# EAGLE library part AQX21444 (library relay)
PhotoMOS Relay NAiS Source: http://www.mew-europe.com/.. pti_en.pdf
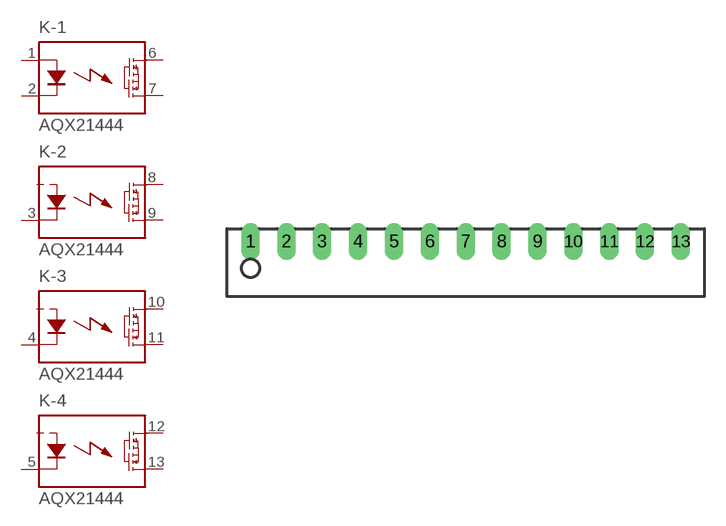
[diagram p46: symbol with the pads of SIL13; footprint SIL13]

Designator prefix K; gates -1=PHOTOMOS_2D -2=PHOTOMOS-DC3 -3=PHOTOMOS-DC3 -4=PHOTOMOS-DC3

## AQX21444 (OC_FARNELL: unknown; OC_NEWARK: unknown)  [SIL13]
1  -1:A  pas
2  -1:K  pas
3  -2:K  pas
4  -3:K  pas
5  -4:K  pas
6  -1:DS1  pas
7  -1:DS2  pas
8  -2:DS1  pas
9  -2:DS2  pas
10  -3:DS1  pas
11  -3:DS2  pas
12  -4:DS1  pas
13  -4:DS2  pas

## Footprint SIL13 (pad centres in mm)
SIL 13 - AQX21.44 Series (Multi-channel) Source: http://www.mew-europe.com/.. pti_en.pdf
drill 0.8 long: 1 -15.24,1.27; 2 -12.7,1.27; 3 -10.16,1.27; 4 -7.62,1.27; 5 -5.08,1.27; 6 -2.54,1.27; 7 0,1.27; 8 2.54,1.27; 9 5.08,1.27; 10 7.62,1.27; 11 10.16,1.27; 12 12.7,1.27; 13 15.24,1.27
